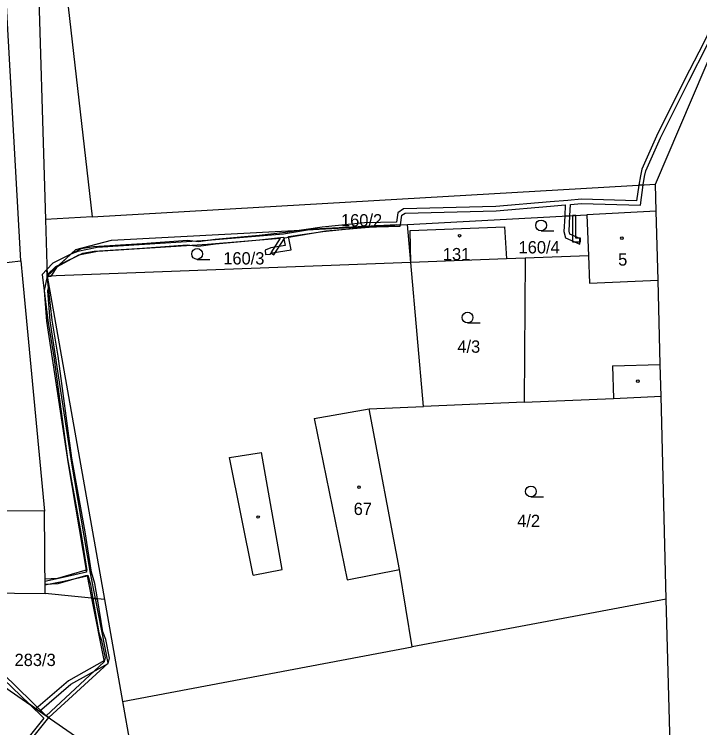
# Model space of a CAD drawing. Extents: x -779723 to -777378, y -1011169 to -1009297.
# Drawn here: x -779222.9 to -779128.1, y -1010214.5 to -1010115.8 of the extents above; entities that cross this region are included whole.
import ezdxf

# ---------------------------------------------------------------- set-up
doc = ezdxf.new("R2010")
doc.units = 0
for name, color, linetype in [('Hranice parcel', 7, 'Continuous'), ('Parcelní čísla', 7, 'Continuous'), ('Vnitřní kresba', 7, 'Continuous'), ('Věcná břemena k části', 7, 'Continuous'), ('Značky budov', 7, 'Continuous'), ('Značky kultur', 7, 'Continuous')]:
    doc.layers.add(name, color=color, linetype=linetype)

msp = doc.modelspace()

# ---------------------------------------------------------------- linework, layer by layer
at = {"layer": 'Hranice parcel'}
for p, q in [((-779134.25, -1010139.27), (-779120.37, -1010106.68)), ((-779212.16, -1010143.8), (-779134.25, -1010139.27)), ((-779134.15, -1010143.02), (-779134.25, -1010139.27)), ((-779212.16, -1010143.8), (-779218.61, -1010144.17)), ((-779168.53, -1010144.84), (-779143.73, -1010143.53)), ((-779134.15, -1010143.02), (-779143.73, -1010143.53)), ((-779218.61, -1010144.17), (-779218.39, -1010152.01)), ((-779168.07, -1010150.12), (-779168.53, -1010144.84)), ((-779168.2, -1010145.69), (-779155.14, -1010145.17)), ((-779168.07, -1010150.12), (-779168.2, -1010145.69)), ((-779155.14, -1010145.17), (-779154.88, -1010149.63)), ((-779225.71, -1010150.28), (-779222.02, -1010149.91)), ((-779154.88, -1010149.63), (-779168.07, -1010150.12)), ((-779152.27, -1010149.53), (-779154.88, -1010149.63)), ((-779152.27, -1010149.53), (-779152.43, -1010169.43)), ((-779168.07, -1010150.12), (-779218.39, -1010152.01)), ((-779166.33, -1010170.02), (-779168.07, -1010150.12)), ((-779218.39, -1010152.01), (-779210.46, -1010196.74)), ((-779132.76, -1010196.68), (-779133.49, -1010168.63)), ((-779152.43, -1010169.43), (-779166.33, -1010170.02)), ((-779218.67, -1010195.92), (-779218.76, -1010184.53)), ((-779210.46, -1010196.74), (-779218.67, -1010195.92)), ((-779210.46, -1010196.74), (-779207.96, -1010210.85)), ((-779132.76, -1010196.68), (-779167.91, -1010203.3)), ((-779132.14, -1010220.3), (-779132.76, -1010196.68)), ((-779207.96, -1010210.85), (-779167.91, -1010203.3)), ((-779207.96, -1010210.85), (-779205.69, -1010223.63))]:
    msp.add_line(p, q, dxfattribs=at)
for points in [[(-779230.18, -1009906.58), (-779238.1, -1009916.55), (-779233.71, -1009966.95), (-779226.79, -1010039.25), (-779219.75, -1010106.05), (-779218.61, -1010144.17)], [(-779229.16, -1009906.17), (-779234.8, -1009917.25), (-779223.59, -1010039.03), (-779218.82, -1010085.26), (-779212.16, -1010143.8)], [(-779222.02, -1010149.91), (-779224.22, -1010110.43), (-779227.75, -1010085.02), (-779232.26, -1010057.56), (-779233.9, -1010041.71)], [(-779143.73, -1010143.53), (-779143.53, -1010149.2), (-779152.27, -1010149.53)], [(-779133.49, -1010168.63), (-779133.6, -1010164.22), (-779133.9, -1010152.56), (-779134.15, -1010143.02)], [(-779218.39, -1010152.01), (-779214.4, -1010148.33), (-779209.48, -1010147.01), (-779168.53, -1010144.84)], [(-779222.02, -1010149.91), (-779221.79, -1010152.36), (-779218.76, -1010184.53)], [(-779152.43, -1010169.43), (-779140.08, -1010168.91), (-779133.49, -1010168.63)], [(-779167.91, -1010203.3), (-779169.66, -1010192.59), (-779173.84, -1010170.34), (-779166.33, -1010170.02)], [(-779218.76, -1010184.53), (-779242.94, -1010184.31), (-779242.9, -1010187.56)], [(-779242.79, -1010195.65), (-779223.48, -1010209.38), (-779213.39, -1010216.37), (-779205.69, -1010223.63)], [(-779242.79, -1010195.65), (-779239.83, -1010195.66), (-779218.67, -1010195.92)]]:
    msp.add_lwpolyline(points, dxfattribs=at)
at = {"layer": 'Vnitřní kresba'}
for p, q in [((-779143.53, -1010149.2), (-779143.39, -1010153)), ((-779143.39, -1010153), (-779133.9, -1010152.56)), ((-779140.21, -1010164.42), (-779133.6, -1010164.22)), ((-779140.21, -1010164.42), (-779140.08, -1010168.91)), ((-779181.46, -1010171.71), (-779173.84, -1010170.34)), ((-779181.46, -1010171.71), (-779176.88, -1010194.03)), ((-779193.17, -1010177.11), (-779188.72, -1010176.41)), ((-779185.87, -1010192.57), (-779188.72, -1010176.41)), ((-779189.9, -1010193.37), (-779193.17, -1010177.11)), ((-779189.9, -1010193.37), (-779185.87, -1010192.57)), ((-779176.88, -1010194.03), (-779169.66, -1010192.59))]:
    msp.add_line(p, q, dxfattribs=at)
at = {"layer": 'Věcná břemena k části'}
for points in [[(-779135.94, -1010139.37), (-779135.77, -1010138.23), (-779135.57, -1010137.43), (-779133.58, -1010132.88), (-779129.66, -1010125.05), (-779127.1, -1010120.05), (-779125.06, -1010115.81), (-779123.42, -1010112.45), (-779122.91, -1010110.97), (-779121.16, -1010108.46), (-779121.06, -1010108.3), (-779120.37, -1010106.68), (-779117.94, -1010102.23), (-779119.71, -1010105.03), (-779121.66, -1010108.12), (-779123.45, -1010110.69), (-779123.98, -1010112.21), (-779125.6, -1010115.55), (-779127.64, -1010119.79), (-779130.2, -1010124.77), (-779134.12, -1010132.62), (-779136.15, -1010137.23), (-779136.35, -1010138.11), (-779136.54, -1010139.4)], [(-779182.9, -1010145.6), (-779169.53, -1010144.89), (-779169.33, -1010143.59), (-779168.89, -1010143.28), (-779156.3, -1010142.98), (-779148.76, -1010142.34), (-779146.73, -1010142.15), (-779146.81, -1010143.69), (-779146.1, -1010143.66), (-779146.02, -1010142.1), (-779144.48, -1010141.98), (-779136.35, -1010142.2), (-779135.94, -1010139.37), (-779136.54, -1010139.4), (-779136.87, -1010141.58), (-779144.5, -1010141.38), (-779146.38, -1010141.52), (-779148.82, -1010141.74), (-779156.34, -1010142.38), (-779169.09, -1010142.68), (-779169.89, -1010143.25), (-779170.08, -1010144.52), (-779174.47, -1010144.62), (-779180.35, -1010145.23)], [(-779146.81, -1010143.69), (-779146.91, -1010145.85), (-779146.7, -1010146.71), (-779144.73, -1010147.58), (-779144.71, -1010146.82), (-779146.1, -1010146.21), (-779146.21, -1010145.79), (-779146.1, -1010143.66)], [(-779145.75, -1010143.64), (-779145.75, -1010147.26), (-779144.62, -1010147.25), (-779144.62, -1010146.75), (-779145.25, -1010146.76), (-779145.25, -1010143.61)], [(-779179.83, -1010145.75), (-779170.07, -1010144.92), (-779181.55, -1010145.53), (-779185.7, -1010146.21), (-779196.22, -1010147.07), (-779211.45, -1010148.03), (-779214.15, -1010148.58), (-779215.11, -1010148.98), (-779216.93, -1010150.67), (-779213.99, -1010149.06), (-779211.39, -1010148.53), (-779196.18, -1010147.56), (-779186.15, -1010146.75), (-779187.44, -1010148.78), (-779187.02, -1010149.04), (-779185.52, -1010146.69)], [(-779216.71, -1010150.46), (-779213.46, -1010148.83), (-779211.87, -1010148.53), (-779205.21, -1010148.12), (-779199, -1010147.68), (-779197.45, -1010147.85), (-779195.08, -1010147.52), (-779189, -1010146.98), (-779185.68, -1010146.6), (-779185.44, -1010147.79), (-779187.43, -1010148.1), (-779188.21, -1010148.41), (-779188.18, -1010148.99), (-779187.48, -1010148.95), (-779187.49, -1010148.88), (-779187.25, -1010148.78), (-779184.62, -1010148.37), (-779184.98, -1010146.51), (-779180.27, -1010145.83), (-779174.43, -1010145.22), (-779169.56, -1010145.1), (-779169.53, -1010144.89), (-779182.9, -1010145.6), (-779185.43, -1010145.97), (-779189.06, -1010146.38), (-779195.14, -1010146.92), (-779197.45, -1010147.25), (-779198.98, -1010147.08), (-779205.25, -1010147.52), (-779211.95, -1010147.93), (-779213.66, -1010148.25), (-779215.11, -1010148.98)], [(-779218.39, -1010151.84), (-779217.17, -1010150.69), (-779216.71, -1010150.46), (-779215.11, -1010148.98), (-779217.57, -1010150.23), (-779218.42, -1010151.11)], [(-779217.82, -1010151.99), (-779216.93, -1010150.67), (-779218.39, -1010152.01)], [(-779211.43, -1010196.64), (-779211.79, -1010194.51), (-779212.25, -1010192.95), (-779213.11, -1010187.39), (-779214.97, -1010177.18), (-779216.84, -1010163.09), (-779217.7, -1010158.1), (-779218.39, -1010152.01), (-779218.39, -1010151.84), (-779218.42, -1010151.11), (-779219.05, -1010151.77), (-779218.3, -1010158.14), (-779217.44, -1010163.19), (-779215.57, -1010177.28), (-779213.71, -1010187.49), (-779212.89, -1010192.71), (-779213.15, -1010192.74), (-779216.95, -1010193.81), (-779218.69, -1010193.92), (-779218.68, -1010194.63), (-779216.83, -1010194.51), (-779213.01, -1010193.42), (-779212.74, -1010193.39), (-779212.37, -1010194.65), (-779212.04, -1010196.58)], [(-779212.23, -1010196.56), (-779211.7, -1010196.62), (-779212.39, -1010193.1), (-779214.98, -1010177.9), (-779217.96, -1010158.17), (-779218.28, -1010154.04), (-779218.15, -1010153.38), (-779218.39, -1010152.01), (-779218.78, -1010154), (-779218.45, -1010158.22), (-779215.47, -1010177.97), (-779212.93, -1010192.96), (-779216.15, -1010193.7), (-779218.68, -1010194.25), (-779218.68, -1010194.73), (-779216.05, -1010194.18), (-779212.84, -1010193.45)], [(-779220.81, -1010211.23), (-779218.5, -1010212.83), (-779226.54, -1010205.05), (-779236.62, -1010198.39), (-779242.2, -1010195.65), (-779242.79, -1010195.65), (-779241.36, -1010196.66), (-779236.86, -1010198.82), (-779226.86, -1010205.45)], [(-779209.93, -1010205.59), (-779209.73, -1010204.83), (-779210.28, -1010202.25), (-779210.66, -1010201.19), (-779211.43, -1010196.64), (-779212.04, -1010196.58), (-779211.24, -1010201.35), (-779210.86, -1010202.41), (-779210.35, -1010204.81), (-779210.45, -1010205.19), (-779215.42, -1010207.97), (-779219.92, -1010211.85), (-779219.41, -1010212.2), (-779215.08, -1010208.47)], [(-779209.95, -1010205.54), (-779211.7, -1010196.62), (-779212.23, -1010196.56), (-779210.49, -1010205.36), (-779218.5, -1010212.83), (-779218.14, -1010213.08)], [(-779218.14, -1010213.08), (-779218.5, -1010212.83), (-779219.41, -1010212.2), (-779219.92, -1010211.85), (-779220.81, -1010211.23), (-779218.81, -1010213.14), (-779222.9, -1010218.24), (-779224.1, -1010219.53), (-779223.57, -1010219.94), (-779222.52, -1010218.56)]]:
    msp.add_lwpolyline(points, close=True, dxfattribs=at)
at = {"layer": 'Značky budov'}
for centre in [(-779161.347, -1010146.419), (-779138.897, -1010146.759), (-779136.697, -1010166.529), (-779175.247, -1010181.199), (-779189.207, -1010185.329)]:
    msp.add_circle(centre, 0.175, dxfattribs=at)
at = {"layer": 'Značky kultur'}
for p, q in [((-779150.073, -1010145.74), (-779148.323, -1010145.74)), ((-779197.633, -1010149.69), (-779195.883, -1010149.69)), ((-779160.243, -1010158.48), (-779158.493, -1010158.48)), ((-779151.483, -1010182.54), (-779149.733, -1010182.54))]:
    msp.add_line(p, q, dxfattribs=at)
for centre in [(-779150.073, -1010144.99), (-779197.633, -1010148.94), (-779160.243, -1010157.73), (-779151.483, -1010181.79)]:
    msp.add_circle(centre, 0.75, dxfattribs=at)

# ---------------------------------------------------------------- texts
at = {"layer": 'Parcelní čísla'}
for s, p in [('160/2', (-779177.74, -1010145.13)), ('160/4', (-779153.19, -1010148.86)), ('160/3', (-779194.02, -1010150.39)), ('131', (-779163.654, -1010149.809)), ('5', (-779139.42, -1010150.549)), ('4/3', (-779161.65, -1010162.6)), ('67', (-779175.99, -1010185.049)), ('4/2', (-779153.38, -1010186.71)), ('283/3', (-779222.88, -1010205.94))]:
    msp.add_text(s, height=1.7, dxfattribs=at).set_placement(p)

doc.saveas('drawing.dxf')
